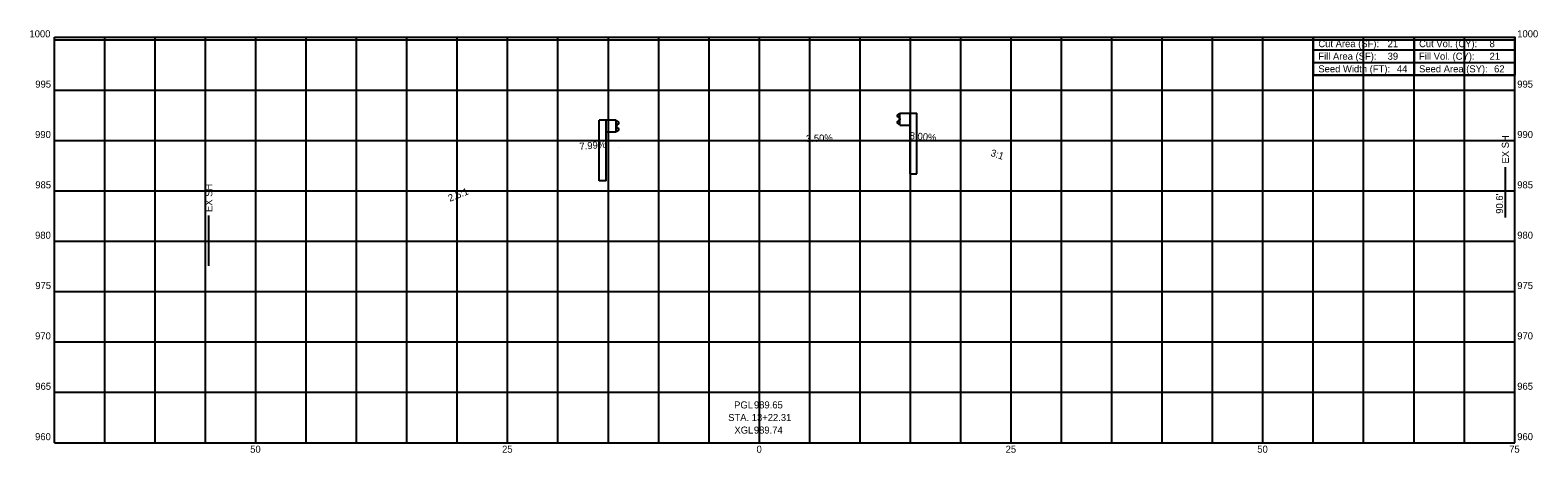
# Model space of a CAD drawing. Extents: x -72 to 77, y 959 to 1001.
import ezdxf

# ---------------------------------------------------------------- set-up
doc = ezdxf.new("R2010")
doc.units = 0
for name, color, linetype in [('Default', 7, 'Continuous'), ('PF_X_Ground_Line', 7, 'Continuous'), ('RD_P_Cells', 7, 'Continuous'), ('RW_X_Esmt_SH', 7, 'Continuous'), ('SH_Major_Grid_Line', 7, 'Continuous'), ('SH_Masking', 7, 'Continuous'), ('SH_Text', 7, 'Continuous')]:
    doc.layers.add(name, color=color, linetype=linetype)

msp = doc.modelspace()

# ---------------------------------------------------------------- linework, layer by layer
at = {"layer": 'Default'}
msp.add_circle((75, 1000.25), 0.000417, dxfattribs=at)
msp.add_circle((75, 1000.25), 0.000417, dxfattribs=at)
msp.add_circle((75, 1000.25), 0.000417, dxfattribs=at)
msp.add_circle((75, 1000.25), 0.000417, dxfattribs=at)
msp.add_circle((75, 1000.25), 0.000417, dxfattribs=at)
msp.add_circle((75, 1000.25), 0.000417, dxfattribs=at)
msp.add_circle((75, 1000.25), 0.000417, dxfattribs=at)
msp.add_circle((75, 1000.25), 0.000417, dxfattribs=at)
msp.add_circle((75, 1000.25), 0.000417, dxfattribs=at)
msp.add_circle((75, 1000.25), 0.000417, dxfattribs=at)
msp.add_circle((75, 1000.25), 0.000417, dxfattribs=at)
msp.add_circle((75, 1000.25), 0.000417, dxfattribs=at)
at = {"layer": 'PF_X_Ground_Line'}
for p, q in [((55, 1000.25), (75, 1000.25)), ((55, 1000.25), (55, 997.75)), ((65, 1000.25), (65, 996.5)), ((75, 1000.25), (75, 997.75)), ((55, 999), (75, 999)), ((55, 997.75), (75, 997.75)), ((63.3, 997.12), (63.3, 997.12)), ((72.95, 997.12), (72.95, 997.12))]:
    msp.add_line(p, q, dxfattribs=at)
msp.add_lwpolyline([(55, 997.75), (55, 996.5), (75, 996.5), (75, 997.75)], dxfattribs=at)
at = {"layer": 'RD_P_Cells'}
for p, q in [((13.86, 992.63), (13.71, 992.52)), ((13.72, 992.51), (13.86, 992.62)), ((13.83, 992.61), (13.83, 992.61)), ((13.84, 992.6), (13.84, 992.6)), ((13.95, 992.64), (13.86, 992.63)), ((13.86, 992.63), (13.86, 992.63)), ((13.86, 992.62), (13.95, 992.63)), ((13.86, 992.62), (13.86, 992.62)), ((13.95, 992.64), (13.95, 992.64)), ((13.95, 992.63), (13.95, 992.64)), ((13.95, 992.63), (13.95, 992.63)), ((13.96, 992.71), (14.96, 992.71)), ((13.96, 991.54), (13.96, 992.71)), ((14.96, 992.71), (15.63, 992.71)), ((14.96, 986.71), (14.96, 992.71)), ((15.63, 986.71), (15.63, 992.71)), ((-15.23, 992.01), (-15.9, 992.01)), ((-15.9, 986.01), (-15.9, 992.01)), ((-14.23, 992.01), (-15.23, 992.01)), ((-15.23, 986.01), (-15.23, 992.01)), ((-14.23, 990.84), (-14.23, 992.01)), ((-14.22, 991.94), (-14.22, 991.94)), ((-14.22, 991.94), (-14.13, 991.92)), ((-14.22, 991.93), (-14.22, 991.94)), ((-14.22, 991.93), (-14.22, 991.93)), ((-14.13, 991.91), (-14.22, 991.93)), ((-14.22, 991.47), (-14.22, 991.47)), ((-14.22, 991.38), (-14.22, 991.47)), ((-14.22, 991.39), (-14.22, 991.46)), ((-14.22, 991.38), (-14.22, 991.38)), ((-14.21, 991.47), (-14.21, 991.47)), ((-14.21, 991.47), (-14.21, 991.38)), ((-14.21, 991.39), (-14.21, 991.46)), ((-14.21, 991.38), (-14.21, 991.38)), ((-14.18, 991.54), (-13.99, 991.68)), ((-14.18, 991.54), (-14.18, 991.54)), ((-14.18, 991.31), (-14.18, 991.31)), ((-13.99, 991.17), (-14.18, 991.31)), ((-13.99, 991.67), (-14.17, 991.53)), ((-14.17, 991.53), (-14.17, 991.53)), ((-14.17, 991.31), (-14.17, 991.31)), ((-14.17, 991.31), (-13.99, 991.18)), ((-14.13, 991.92), (-14.13, 991.92)), ((-14.13, 991.92), (-13.99, 991.81)), ((-14.13, 991.91), (-14.13, 991.91)), ((-13.99, 991.81), (-14.13, 991.91)), ((-14.11, 991.9), (-14.11, 991.9)), ((-14.11, 991.9), (-14.11, 991.9)), ((-14.11, 991.59), (-14.11, 991.59)), ((-14.11, 991.58), (-14.11, 991.58)), ((-13.99, 991.81), (-13.99, 991.81)), ((-13.99, 991.81), (-13.99, 991.81)), ((-13.99, 991.68), (-13.99, 991.68)), ((-13.99, 991.67), (-13.99, 991.67)), ((-13.99, 991.18), (-13.99, 991.18)), ((-13.99, 991.17), (-13.99, 991.17)), ((-13.96, 991.74), (-13.96, 991.74)), ((-13.96, 991.11), (-13.96, 991.11)), ((-13.95, 991.74), (-13.95, 991.74)), ((-13.95, 991.11), (-13.95, 991.11)), ((13.68, 992.45), (13.68, 992.45)), ((13.68, 991.81), (13.68, 991.81)), ((13.69, 992.45), (13.69, 992.45)), ((13.69, 991.81), (13.69, 991.81)), ((13.71, 992.52), (13.71, 992.52)), ((13.9, 992.02), (13.71, 991.88)), ((13.71, 991.88), (13.71, 991.88)), ((13.71, 991.74), (13.71, 991.74)), ((13.71, 991.74), (13.86, 991.63)), ((13.72, 992.51), (13.72, 992.51)), ((13.72, 992.38), (13.72, 992.38)), ((13.72, 992.38), (13.72, 992.38)), ((13.91, 992.25), (13.72, 992.38)), ((13.72, 992.38), (13.9, 992.24)), ((13.72, 991.87), (13.91, 992.01)), ((13.72, 991.87), (13.72, 991.87)), ((13.72, 991.75), (13.72, 991.75)), ((13.86, 991.64), (13.72, 991.75)), ((13.84, 992.3), (13.84, 992.3)), ((13.84, 992.29), (13.84, 992.29)), ((13.94, 991.63), (13.86, 991.64)), ((13.86, 991.63), (13.94, 991.62)), ((13.9, 992.24), (13.9, 992.24)), ((13.9, 992.02), (13.9, 992.02)), ((13.91, 992.25), (13.91, 992.25)), ((13.91, 992.01), (13.91, 992.01)), ((13.93, 992.17), (13.93, 992.17)), ((13.93, 992.17), (13.93, 992.08)), ((13.93, 992.1), (13.93, 992.16)), ((13.93, 992.08), (13.93, 992.08)), ((13.94, 992.17), (13.94, 992.17)), ((13.94, 992.08), (13.94, 992.17)), ((13.94, 992.1), (13.94, 992.16)), ((13.94, 992.08), (13.94, 992.08)), ((13.94, 991.63), (13.94, 991.63)), ((13.94, 991.62), (13.94, 991.63)), ((13.94, 991.62), (13.94, 991.62)), ((13.96, 991.54), (14.96, 991.54)), ((-14.23, 990.84), (-15.23, 990.84)), ((-14.21, 990.92), (-14.13, 990.94)), ((-14.13, 990.93), (-14.21, 990.91)), ((-14.21, 990.92), (-14.21, 990.92)), ((-14.21, 990.91), (-14.21, 990.92)), ((-14.21, 990.91), (-14.21, 990.91)), ((-14.13, 990.94), (-13.99, 991.04)), ((-13.98, 991.04), (-14.13, 990.93)), ((-13.99, 991.04), (-13.99, 991.04)), ((-13.98, 991.04), (-13.98, 991.04)), ((13.68, 990.05), (13.68, 990.05)), ((-13.95, 989.34), (-13.95, 989.34)), ((14.96, 986.71), (15.63, 986.71)), ((-15.23, 986.01), (-15.9, 986.01))]:
    msp.add_line(p, q, dxfattribs=at)
for points in [[(-14.2, 991.48), (-14.2, 991.36), (-14.21, 991.36), (-14.21, 991.48)], [(-14.2, 991.45), (-14.2, 991.39), (-14.17, 991.39), (-14.17, 991.45)], [(13.93, 992.16), (13.93, 992.1), (13.9, 992.1), (13.9, 992.16)], [(13.93, 992.19), (13.93, 992.07), (13.93, 992.07), (13.93, 992.19)]]:
    msp.add_lwpolyline(points, close=True, dxfattribs=at)
for centre, radius, start, end in [((-14.13, 991.47), 0.0886, 126.318, 180.0944), ((-14.13, 991.38), 0.0886, 180.0944, 233.8707), ((-14.13, 991.47), 0.0788, 126.318, 180.0944), ((-14.13, 991.38), 0.0788, 180.0944, 233.8707), ((-14.04, 991.74), 0.0787, 306.318, 53.2212), ((-14.04, 991.74), 0.0886, 306.318, 53.2212), ((-14.04, 991.11), 0.0886, 306.9675, 53.8707), ((-14.04, 991.11), 0.0787, 306.9675, 53.8707), ((13.77, 992.45), 0.0886, 126.7788, 233.682), ((13.77, 991.81), 0.0886, 126.1293, 233.0325), ((13.77, 992.45), 0.0787, 126.7788, 233.682), ((13.77, 991.81), 0.0787, 126.1293, 233.0325), ((13.86, 992.17), 0.0788, 359.9056, 53.682), ((13.86, 992.08), 0.0788, 306.1293, 359.9056), ((13.86, 992.17), 0.0886, 359.9056, 53.682), ((13.86, 992.08), 0.0886, 306.1293, 359.9056)]:
    msp.add_arc(centre, radius, start, end, dxfattribs=at)
at = {"layer": 'RW_X_Esmt_SH'}
for p, q in [((74.07, 982.37), (74.07, 987.37)), ((-54.67, 977.55), (-54.67, 982.55))]:
    msp.add_line(p, q, dxfattribs=at)
at = {"layer": 'SH_Major_Grid_Line'}
for p, q in [((-70, 1000.25), (75, 1000.25)), ((-70, 960), (-70, 1000.25)), ((-65, 960), (-65, 1000.25)), ((-60, 960), (-60, 1000.25)), ((-55, 960), (-55, 1000.25)), ((-50, 960), (-50, 1000.25)), ((-45, 960), (-45, 1000.25)), ((-40, 960), (-40, 1000.25)), ((-35, 960), (-35, 1000.25)), ((-30, 960), (-30, 1000.25)), ((-25, 960), (-25, 1000.25)), ((-20, 960), (-20, 1000.25)), ((-15, 960), (-15, 1000.25)), ((-10, 960), (-10, 1000.25)), ((-5, 960), (-5, 1000.25)), ((0, 960), (0, 1000.25)), ((5, 960), (5, 1000.25)), ((10, 960), (10, 1000.25)), ((15, 960), (15, 1000.25)), ((20, 960), (20, 1000.25)), ((25, 960), (25, 1000.25)), ((30, 960), (30, 1000.25)), ((35, 960), (35, 1000.25)), ((40, 960), (40, 1000.25)), ((45, 960), (45, 1000.25)), ((50, 960), (50, 1000.25)), ((55, 960), (55, 1000.25)), ((60, 960), (60, 1000.25)), ((65, 960), (65, 1000.25)), ((70, 960), (70, 1000.25)), ((75, 960), (75, 1000.25)), ((-70, 1000), (75, 1000)), ((-70, 995), (75, 995)), ((-70, 990), (75, 990)), ((-70, 985), (75, 985)), ((-70, 980), (75, 980)), ((-70, 975), (75, 975)), ((-70, 970), (75, 970)), ((-70, 965), (75, 965)), ((-70, 960), (75, 960))]:
    msp.add_line(p, q, dxfattribs=at)
at = {"layer": 'SH_Masking'}
msp.add_lwpolyline([(55, 1000.25), (75, 1000.25), (75, 996.5), (55, 996.5)], close=True, dxfattribs=at)

# ---------------------------------------------------------------- texts
at = {"layer": 'RW_X_Esmt_SH'}
for p in [(74.42, 987.72), (-54.32, 982.9)]:
    msp.add_text('EX SH', height=0.7, rotation=90, dxfattribs=at).set_placement(p)
at = {"layer": 'SH_Text'}
for s, p in [('1000', (-72.48, 1000.25)), ('1000', (75.25, 1000.25)), ('Cut Area (SF):', (55.5, 999.27)), ('Fill Area (SF):', (55.5, 998.02)), ('39', (62.38, 998.02)), ('21', (62.38, 999.27)), ('Cut Vol. (CY):', (65.5, 999.27)), ('Fill Vol. (CY):', (65.5, 998.02)), ('8', (72.5, 999.27)), ('21', (72.5, 998.02)), ('Seed Width (FT):', (55.5, 996.77)), ('44', (63.3, 996.77)), ('Seed Area (SY):', (65.5, 996.77)), ('62', (72.95, 996.77)), ('995', (-71.9, 995.25)), ('995', (75.25, 995.25)), ('990', (-71.92, 990.25)), ('990', (75.25, 990.25)), ('985', (-71.9, 985.25)), ('985', (75.25, 985.25)), ('980', (-71.92, 980.25)), ('980', (75.25, 980.25)), ('975', (-71.9, 975.25)), ('975', (75.25, 975.25)), ('970', (-71.92, 970.25)), ('970', (75.25, 970.25)), ('965', (-71.9, 965.25)), ('965', (75.25, 965.25)), ('STA. 13+22.31', (-3.1, 962.15)), ('PGL ', (-2.51, 963.4)), ('989.65', (-0.54, 963.4)), ('XGL ', (-2.48, 960.9)), ('989.74', (-0.55, 960.9)), ('960', (-71.92, 960.25)), ('50', (-50.56, 959)), ('25', (-25.55, 959)), ('0', (-0.28, 959)), ('25', (24.45, 959)), ('50', (49.44, 959)), ('75', (74.45, 959)), ('960', (75.25, 960.25))]:
    msp.add_text(s, height=0.7, dxfattribs=at).set_placement(p)
for s, rotation, p in [('7.99%', 4.5673, (-17.84, 989.07)), ('3.50%', 2.0045, (4.64, 989.84)), ('8.00%', 355.4261, (14.9, 990.15)), ('3:1', 341.5668, (22.9, 988.49)), ('2.5:1', 21.9913, (-30.74, 983.91)), ("90.6'", 90, (73.84, 982.73))]:
    msp.add_text(s, height=0.7, rotation=rotation, dxfattribs=at).set_placement(p)

doc.saveas('drawing.dxf')
